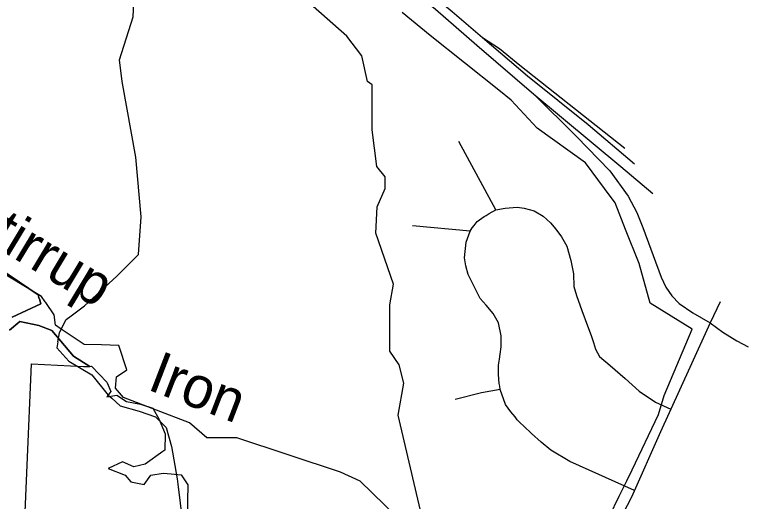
# Model space of a CAD drawing. Extents: x 2001466 to 31450019, y -30647475 to 847247.
# Drawn here: x 31441239 to 31446537, y -30628458 to -30624939 of the extents above; entities that cross this region are included whole.
import ezdxf

# ---------------------------------------------------------------- set-up
doc = ezdxf.new("R2010")
doc.units = 0
for name, color, linetype in [('Exist Boundary Political City Limit New', 7, 'Continuous'), ('Exist Hydrographic Creek Single Shore', 7, 'Continuous'), ('Exist Hydrographic Creek Single Shore Label', 7, 'Continuous'), ('Exist Road Non-System Type 51', 7, 'Continuous'), ('Exist Road Primary Interstate Divided Center Attributed', 7, 'Continuous'), ('Exist Road Primary Interstate Ramp 1 Lane Attributed', 7, 'Continuous'), ('Exist Road Secondary Type 51 Attributed', 7, 'Continuous'), ('Map Preparation Boundary City Limit Buffer Line', 7, 'Continuous')]:
    doc.layers.add(name, color=color, linetype=linetype)

msp = doc.modelspace()

# ---------------------------------------------------------------- linework, layer by layer
at = {"layer": 'Exist Boundary Political City Limit New'}
for points in [[(31445534.8, -30628565.2), (31445603.3, -30628419.8), (31445659.6, -30628309.2), (31445697.9, -30628228.9), (31445888.3, -30627829), (31445928.4, -30627692.5), (31446131.3, -30627212.6), (31445827.8, -30627024.1), (31445749, -30626738), (31445651, -30626491.3), (31445574.6, -30626299.6), (31445499.1, -30626196.8), (31445362.3, -30626010.6), (31445011.6, -30625761.1), (31444825.3, -30625558.5), (31444734, -30625485.5), (31444238.5, -30625089), (31444036, -30624924)], [(31441128.9, -30626776.1), (31441408, -30626965.1), (31441416.6, -30626993.6), (31441416.9, -30626994.1), (31441427.9, -30627030.1), (31441221.4, -30627126.1)], [(31441201.4, -30627219.1), (31441276.3, -30627158.4), (31441412.8, -30627185.6), (31441506, -30627222.3), (31441664.1, -30627408.9), (31441782.5, -30627481.7)], [(31441782.5, -30627481.7), (31441793.8, -30627480.1), (31441905.3, -30627596.6), (31441907, -30627600.7), (31441933.5, -30627663.5), (31441904.1, -30627702), (31441975.3, -30627691), (31442046.4, -30627736.5), (31442147.4, -30627755.3), (31442237.3, -30627783.5), (31442282.4, -30627866.1), (31442325.3, -30627969.3), (31442322.8, -30628086.9), (31442308.5, -30628097.1), (31442181, -30628189.1), (31442098.9, -30628208.8), (31442016.3, -30628172.1), (31441912.9, -30628219), (31442037.3, -30628269.5), (31442078.3, -30628317.6), (31442174.3, -30628335.2), (31442221.4, -30628268.5), (31442309.8, -30628253.6), (31442369.5, -30628258.8), (31442442.1, -30628265), (31442489.5, -30628337), (31442484.1, -30628573.1)]]:
    msp.add_lwpolyline(points, dxfattribs=at)
at = {"layer": 'Exist Hydrographic Creek Single Shore'}
for p, q in [((31441463.4, -30627020.9), (31441459.5, -30627015.2)), ((31441523.3, -30627108.8), (31441463.4, -30627020.9))]:
    msp.add_line(p, q, dxfattribs=at)
for points in [[(31443820.3, -30625446.4), (31443787.3, -30625422.7), (31443745.5, -30625238.1), (31443636.4, -30625094.8), (31443394.4, -30624879.9), (31443152.5, -30624773.2), (31443044.4, -30624646.3), (31442802.4, -30624572.4), (31442685.4, -30624448.6), (31442602.3, -30624273.1), (31442451.4, -30624122.4), (31442292.5, -30623817.2), (31442300.5, -30623715.7), (31442374.5, -30623574.2)], [(31444008.4, -30627835.5), (31444049.4, -30627603.4), (31444015.3, -30627471.4), (31443948.5, -30627371.7), (31443948.5, -30627037), (31443973.5, -30626886.6), (31443847.4, -30626519.8), (31443855.4, -30626329.7), (31443913.4, -30626196.3), (31443913.4, -30626111), (31443854.4, -30626037.6), (31443821.4, -30625771.2), (31443820.3, -30625446.4)], [(31441459.5, -30627015.2), (31441432.5, -30626975.7), (31441072.1, -30626758.9)], [(31441575.3, -30627212.9), (31441532.4, -30627184.4), (31441523.3, -30627108.8)], [(31441865.4, -30627325.8), (31441741.5, -30627323.2), (31441575.3, -30627212.9)], [(31442049.5, -30627506.7), (31441991.5, -30627331.6), (31441865.4, -30627325.8)], [(31444201.3, -30628702.3), (31444084.4, -30628654.1), (31443734.4, -30628312.2), (31443592.3, -30628246.9), (31442842.4, -30627998.7), (31442625.5, -30627997.5), (31442500.4, -30627890), (31442024.5, -30627706.4), (31441966.5, -30627639.5), (31441974.4, -30627557.6), (31442049.5, -30627506.7)], [(31444201.3, -30628702.3), (31444176.5, -30628554.2), (31444008.4, -30627835.5)]]:
    msp.add_lwpolyline(points, dxfattribs=at)
at = {"layer": 'Exist Road Non-System Type 51'}
for p, q in [((31444712.6, -30626350.6), (31444446.9, -30625855.5)), ((31444528.1, -30626504.4), (31444112.3, -30626466)), ((31441939.5, -30627712.8), (31442001, -30627767.6)), ((31442254.8, -30627845.8), (31442332.9, -30627923.9))]:
    msp.add_line(p, q, dxfattribs=at)
for points in [[(31441646.7, -30627115.6), (31441742.3, -30627044.7), (31441976.6, -30626829.8), (31442132.8, -30626673.5), (31442152.3, -30626399.9), (31442113.3, -30625970.1), (31442015.7, -30625423), (31441996.1, -30625266.7), (31442093.8, -30624954.1), (31442106.7, -30624705.8), (31442090.2, -30624540.7), (31442068.2, -30624488.4), (31442054.5, -30624444.4), (31442032.5, -30624403.1), (31442005, -30624359.1), (31441966.5, -30624312.3), (31441933.5, -30624276.6), (31441865.3, -30624232.5), (31441791, -30624188.5)], [(31444528.1, -30626504.4), (31444543.1, -30626481), (31444556.5, -30626464.3), (31444579.8, -30626434.2), (31444628.2, -30626399.1), (31444643.3, -30626390.8), (31444665, -30626375.7), (31444712.6, -30626350.6)], [(31444712.6, -30626350.6), (31444781.8, -30626337.3), (31444867, -30626330.6), (31444918.8, -30626339), (31444990.5, -30626357.4), (31445055.7, -30626395.8), (31445107.4, -30626444.2), (31445145.8, -30626489.3), (31445187.6, -30626544.5), (31445226, -30626613), (31445256, -30626716.6), (31445274.4, -30626811.8), (31445276.1, -30626905.4), (31445296.1, -30626968.9), (31445334.5, -30627079.1), (31445376.2, -30627189.4), (31445401.3, -30627259.6), (31445418, -30627309.7), (31445433, -30627358.2), (31445461.4, -30627411.6), (31445539.9, -30627475.1), (31445648.4, -30627568.7), (31445748.6, -30627662.2), (31445867.1, -30627740.8), (31445977.6, -30627791.8)], [(31444745.1, -30627648.9), (31444741.8, -30627625.5), (31444738.4, -30627605.4), (31444731.8, -30627540.3), (31444733.4, -30627505.2), (31444733.4, -30627473.4), (31444740.1, -30627430), (31444744.1, -30627394), (31444751.8, -30627341.5), (31444751.8, -30627261.3), (31444731.8, -30627167.7), (31444695, -30627099.2), (31444643.3, -30627039), (31444601.5, -30626990.6), (31444563.1, -30626918.7), (31444514.7, -30626818.5), (31444498, -30626755), (31444488, -30626696.5), (31444499.7, -30626582.9), (31444528.1, -30626504.4)], [(31441575.3, -30627212.9), (31441610.5, -30627142.4), (31441646.7, -30627115.6)], [(31441550.1, -30627304.2), (31441561.7, -30627240.1), (31441575.3, -30627212.9)], [(31441550.1, -30627304.2), (31441542.2, -30627347.5), (31441630.1, -30627445.2), (31441796, -30627542.9), (31441913.2, -30627689.5), (31441939.5, -30627712.8)], [(31444745.1, -30627648.9), (31444609.9, -30627673.9), (31444419.5, -30627722.4)], [(31445714.5, -30628379.4), (31445247.3, -30628170.2), (31445110.4, -30628088.3), (31445040.3, -30628029.8), (31444970.2, -30627968), (31444915.1, -30627914.5), (31444888.4, -30627889.5), (31444868.3, -30627867.8), (31444852, -30627847.7), (31444821.9, -30627810.9), (31444783.5, -30627757.5), (31444745.1, -30627648.9)], [(31442001, -30627767.6), (31442137.7, -30627806.7), (31442254.8, -30627845.8)], [(31442332.9, -30627923.9), (31442372, -30628060.7), (31442411, -30628295.1), (31442415.7, -30628332.5)], [(31442415.7, -30628332.5), (31442450.1, -30628607.7), (31442479.4, -30628685.9), (31442503.4, -30628709.9)]]:
    msp.add_lwpolyline(points, dxfattribs=at)
at = {"layer": 'Exist Road Primary Interstate Divided Center Attributed'}
for points in [[(31442660.8, -30623560.6), (31443072.2, -30623897.3), (31443571.5, -30624309.9), (31443815.4, -30624516.5), (31444278.8, -30624900.7), (31444576, -30625158.8), (31444987.3, -30625514.2)], [(31445381, -30625735.7), (31444941.9, -30625384.3), (31444616.5, -30625107.3), (31444397.7, -30624919.1), (31444039.8, -30624621.3), (31443703.3, -30624335.7), (31443088.6, -30623831.3), (31442906.5, -30623678.1)], [(31444987.3, -30625514.2), (31445617.3, -30626038), (31445846.7, -30626231.3)], [(31445714.9, -30626019.7), (31445381, -30625735.7)]]:
    msp.add_lwpolyline(points, dxfattribs=at)
at = {"layer": 'Exist Road Primary Interstate Ramp 1 Lane Attributed'}
for points in [[(31445644.4, -30625906.5), (31444888, -30625306.5), (31444739.1, -30625187.6), (31444616.5, -30625107.3)], [(31444987.3, -30625514.2), (31445296.8, -30625821.3), (31445537.6, -30626069.5), (31445669.5, -30626252.6), (31445731.2, -30626370), (31445774.7, -30626477.7), (31445908.6, -30626836.7), (31445940.2, -30626909.7), (31445983.8, -30626971.5), (31446036.5, -30627026.4), (31446137.2, -30627095.7), (31446260.9, -30627167.5)], [(31446260.9, -30627167.5), (31446354, -30627234.2), (31446453, -30627297.5), (31446537.1, -30627339.6)]]:
    msp.add_lwpolyline(points, dxfattribs=at)
at = {"layer": 'Exist Road Secondary Type 51 Attributed'}
for points in [[(31446334.4, -30627014.2), (31446260.9, -30627167.5)], [(31446260.9, -30627167.5), (31446114.7, -30627489.6), (31445903.8, -30627954.2), (31445693, -30628427.7), (31445569.1, -30628667.7), (31445409.8, -30628903.6), (31445300.3, -30629035.7), (31445142.6, -30629164.5), (31444622.8, -30629509.1), (31444083.6, -30629864.3), (31443671.6, -30630134.8), (31443250, -30630426.3), (31443037.5, -30630585.8), (31442871.8, -30630768.5), (31442752.7, -30630907), (31442627.1, -30631116.4), (31442471, -30631501.3), (31442274.7, -30631972.4), (31442081.6, -30632355.7), (31441775.8, -30632944.3)]]:
    msp.add_lwpolyline(points, dxfattribs=at)
at = {"layer": 'Map Preparation Boundary City Limit Buffer Line'}
for points in [[(31445534.8, -30628565.2), (31445603.3, -30628419.8), (31445659.6, -30628309.2), (31445697.9, -30628228.9), (31445888.3, -30627829), (31445928.4, -30627692.5), (31446131.3, -30627212.6), (31445827.8, -30627024.1), (31445749, -30626738), (31445651, -30626491.3), (31445574.6, -30626299.6), (31445499.1, -30626196.8), (31445362.3, -30626010.6), (31445011.6, -30625761.1), (31444825.3, -30625558.5), (31444734, -30625485.5), (31444238.5, -30625089), (31444036, -30624924)], [(31441221.4, -30627126.1), (31441427.9, -30627030.1), (31441416.9, -30626994.1), (31441416.6, -30626993.6), (31441408, -30626965.1), (31441128.9, -30626776.1)], [(31441128.9, -30626776.1), (31441408, -30626965.1), (31441416.6, -30626993.6), (31441416.9, -30626994.1), (31441427.9, -30627030.1), (31441221.4, -30627126.1)], [(31441782.5, -30627481.7), (31441664.1, -30627408.9), (31441506, -30627222.3), (31441412.8, -30627185.6), (31441276.3, -30627158.4), (31441201.4, -30627219.1)], [(31441201.4, -30627219.1), (31441276.3, -30627158.4), (31441412.8, -30627185.6), (31441506, -30627222.3), (31441664.1, -30627408.9), (31441782.5, -30627481.7)], [(31442675.3, -30628674.3), (31442673.8, -30628723.6), (31442667, -30628945), (31442077.4, -30628936.6), (31441675.8, -30628930.8), (31441415.8, -30628927.1), (31441296.3, -30628928.2), (31441360, -30627462.6), (31441735.9, -30627482.1), (31441768.4, -30627483.8), (31441782.5, -30627481.7)], [(31441782.5, -30627481.7), (31441793.8, -30627480.1), (31441905.3, -30627596.6), (31441907, -30627600.7), (31441933.5, -30627663.5), (31441904.1, -30627702), (31441975.3, -30627691), (31442046.4, -30627736.5), (31442147.4, -30627755.3), (31442237.3, -30627783.5), (31442282.4, -30627866.1), (31442325.3, -30627969.3), (31442322.8, -30628086.9), (31442308.5, -30628097.1), (31442181, -30628189.1), (31442098.9, -30628208.8), (31442016.3, -30628172.1), (31441912.9, -30628219), (31442037.3, -30628269.5), (31442078.3, -30628317.6), (31442174.3, -30628335.2), (31442221.4, -30628268.5), (31442309.8, -30628253.6), (31442369.5, -30628258.8), (31442442.1, -30628265), (31442489.5, -30628337), (31442484.1, -30628573.1)]]:
    msp.add_lwpolyline(points, dxfattribs=at)

# ---------------------------------------------------------------- texts
at = {"layer": 'Exist Hydrographic Creek Single Shore Label'}
for s, rotation, p in [('Stirrup', 328.9791, (31440821, -30626454.7)), ('Iron', 338.9021, (31442187.6, -30627646))]:
    msp.add_text(s, height=300, rotation=rotation, dxfattribs=at).set_placement(p)

doc.saveas('drawing.dxf')
